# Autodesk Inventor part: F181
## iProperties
Category: Hand Tools
Company: Mountain Blue Industries Ltd.
Shininess: 64.0
Length Units: 11272
Angle Units: 11279
Time Units: 11290
Mass Units: 11286
Length Display Precision: 3
Angle Display Precision: 2
Compacted: True
Part Number: F181
Document SubType Name: Modeling
Created: 2003-11
Designer: QBZ
Manufacturer: Standard
Standards Organization: Custom
Description: 3/8x9/16 Shallow 12pt Socket
Vendor: Snap-On
Material: Steel, Mild
Density: 0.0
Volumn: 0.0
Area: 0.0
PropertySet Name: Model Information
Control State: 0
Master: False
Checked Out: False
Length: 1
Author: QBZ
Title: 3/8 Shallow 12pt Sockets
Revision Number: A
Keywords: Sockets
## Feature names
1. Revolution1
2. Extrusion1
3. Hole1
4. Extrusion2
5. Circular Pattern1
6. Fillet1
7. Fillet3
8. Fillet5
9. Body Rev [Revolution]
10. Fillet4
